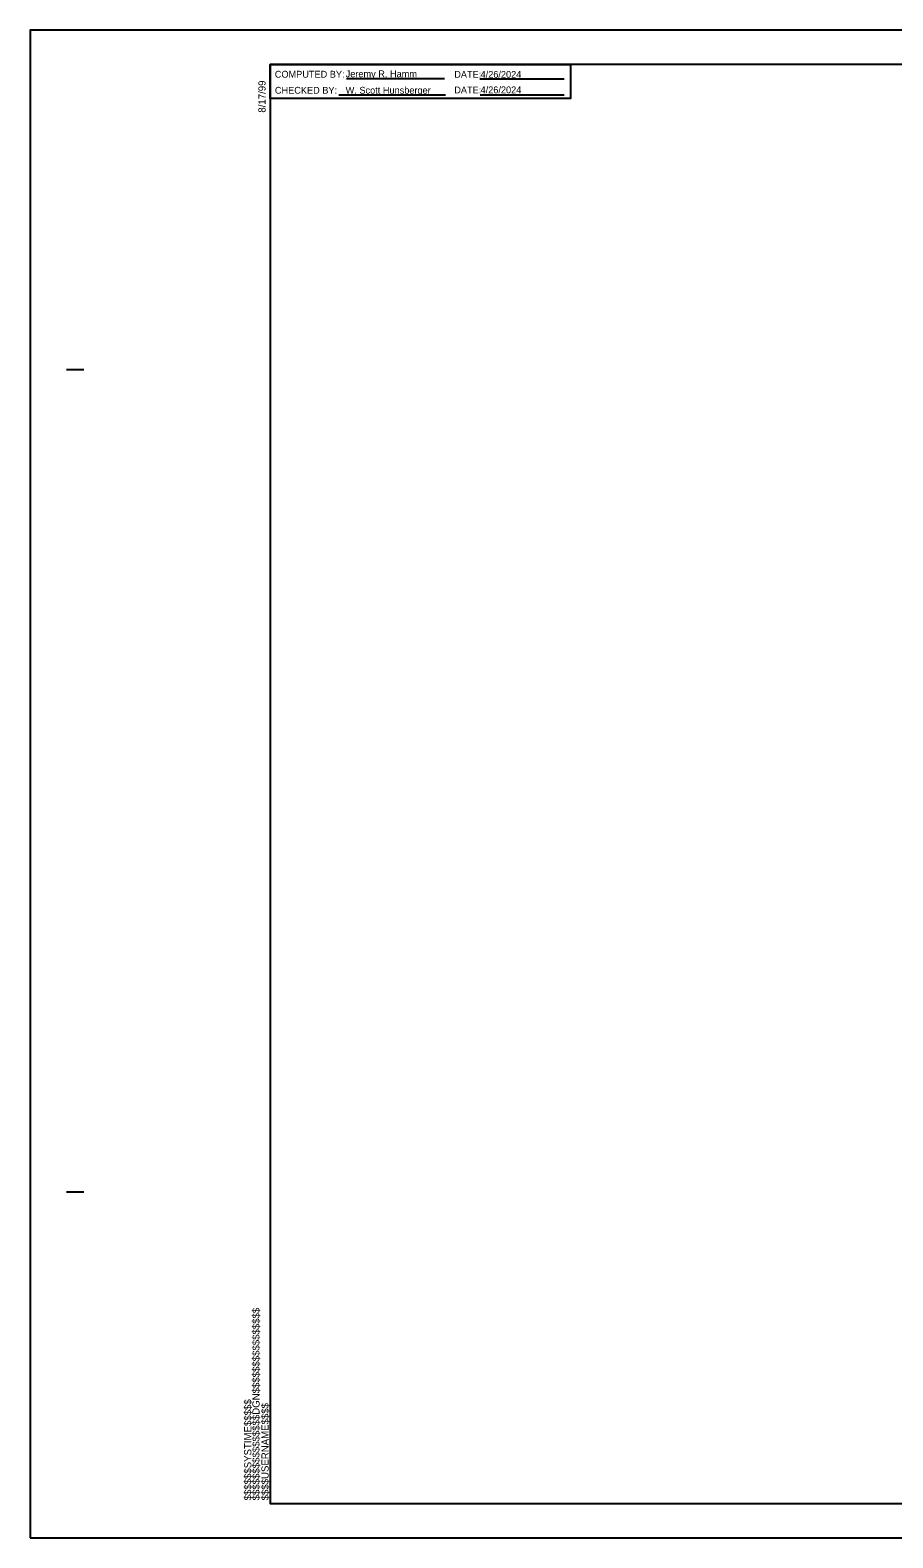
# Model space of a CAD drawing. Extents: x 573680 to 575380, y -54660 to -53560.
# Drawn here: x 573680 to 574309, y -54660 to -53560 of the extents above; entities that cross this region are included whole.
import ezdxf

# ---------------------------------------------------------------- set-up
doc = ezdxf.new("R2010")
doc.units = 0
for name, color, linetype in [('Sheet Block System Information CELL', 7, 'Continuous'), ('Sheet Data Field CELL', 7, 'Continuous'), ('Sheet Plan And Profile CELL', 7, 'Continuous'), ('Sheet Plot Border Outside CELL', 7, 'Continuous'), ('Sheet Summary Guardrail CELL', 7, 'Continuous')]:
    doc.layers.add(name, color=color, linetype=linetype)

msp = doc.modelspace()

# ---------------------------------------------------------------- linework, layer by layer
at = {"layer": 'Sheet Block System Information CELL'}
msp.add_line((573854.9, -54634.7), (573854.9, -54634.7), dxfattribs=at)
at = {"layer": 'Sheet Plan And Profile CELL'}
for p, q in [((573706.4, -53807.2), (573718.9, -53807.2)), ((573706.4, -54407.2), (573718.9, -54407.2)), ((573854.9, -54634.7), (573854.9, -54634.7)), ((573854.9, -54634.7), (573854.9, -54634.7)), ((573854.9, -54634.7), (573854.9, -54634.7)), ((573854.9, -54634.7), (573854.9, -54634.7)), ((573854.9, -54634.7), (573854.9, -54634.7))]:
    msp.add_line(p, q, dxfattribs=at)
msp.add_lwpolyline([(575354.9, -53584.7), (573854.9, -53584.7), (573854.9, -54634.7), (575354.9, -54634.7)], close=True, dxfattribs=at)
at = {"layer": 'Sheet Plot Border Outside CELL'}
msp.add_lwpolyline([(573679.9, -54659.7), (575379.9, -54659.7), (575379.9, -53559.7), (573679.9, -53559.7)], close=True, dxfattribs=at)
at = {"layer": 'Sheet Summary Guardrail CELL'}
for p, q in [((573910.5, -53595.1), (573982.1, -53595.1)), ((574007.9, -53595.3), (574069.3, -53595.3)), ((573905.1, -53606.8), (573982.8, -53606.8)), ((574008, -53606.8), (574069.4, -53606.8))]:
    msp.add_line(p, q, dxfattribs=at)
msp.add_lwpolyline([(573854.9, -53584.7), (574073.9, -53584.7), (574073.9, -53609.7), (573854.9, -53609.7)], close=True, dxfattribs=at)

# ---------------------------------------------------------------- texts
at = {"layer": 'Sheet Block System Information CELL'}
for s, p in [('$$$$$$$$$$$$$$$$DGN$$$$$$$$$$$$$$$$', (573847.2, -54632.4)), ('$$$$$$SYSTIME$$$$$', (573841.2, -54632.4)), ('$$$$USERNAME$$$$', (573853.8, -54632.4))]:
    msp.add_text(s, height=5.25, rotation=90, dxfattribs=at).set_placement(p)
at = {"layer": 'Sheet Data Field CELL'}
for s, p in [('Jeremy R. Hamm', (573910, -53594.1)), ('4/26', (574008.4, -53594.5)), ('/2024', (574021.4, -53594.5)), ('W. Scott Hunsberger', (573910, -53606.1)), ('4/26', (574008.4, -53605.8)), ('/2024', (574021.4, -53605.8))]:
    msp.add_text(s, height=5, dxfattribs=at).set_placement(p)
at = {"layer": 'Sheet Plan And Profile CELL'}
msp.add_text('8/17/99', height=5.25, rotation=90, dxfattribs=at).set_placement((573851.6, -53619.9))
at = {"layer": 'Sheet Summary Guardrail CELL'}
for s, p in [('COMPUTED BY:', (573858.3, -53594.4)), ('DATE:', (573989.2, -53594.5)), ('CHECKED BY:', (573858.4, -53606.1)), ('DATE:', (573989.2, -53605.9))]:
    msp.add_text(s, height=5, dxfattribs=at).set_placement(p)

doc.saveas('drawing.dxf')
